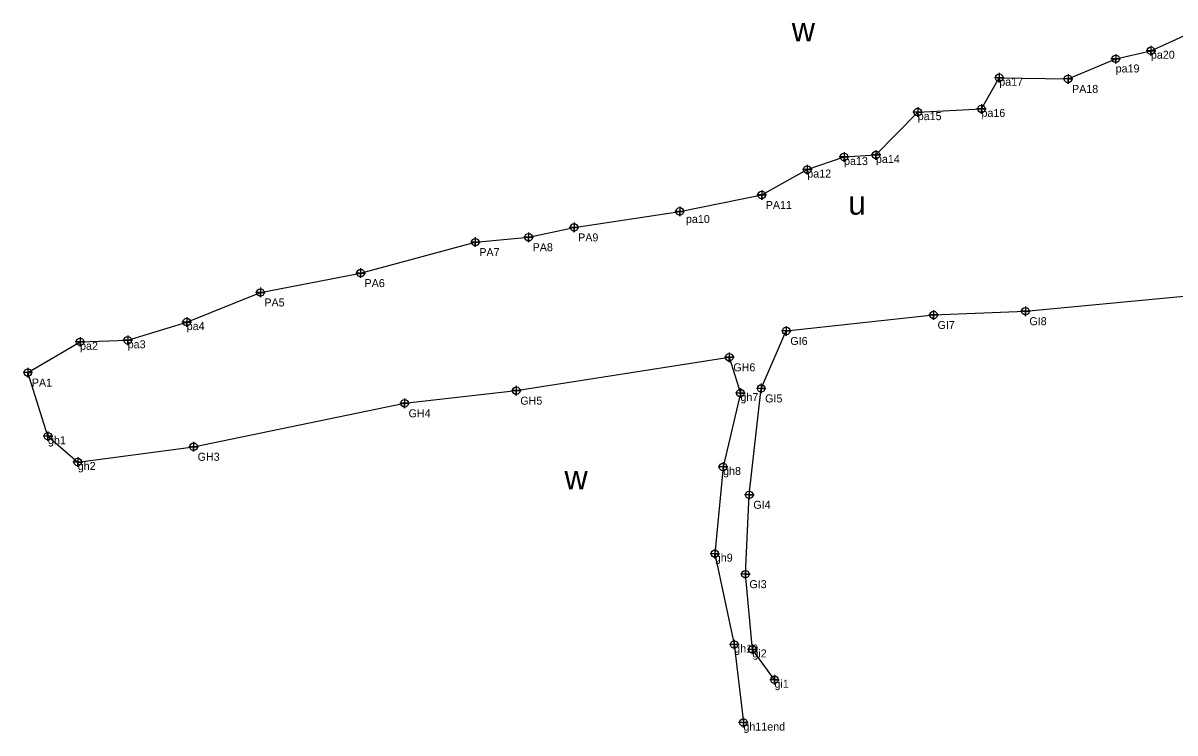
# Model space of a CAD drawing. Extents: x 2184390 to 2187551, y 452846 to 453752.
# Drawn here: x 2186121 to 2186840, y 453160 to 453604 of the extents above; entities that cross this region are included whole.
import ezdxf

# ---------------------------------------------------------------- set-up
doc = ezdxf.new("R2010")
doc.units = 0
for name, color, linetype in [('Exist Environmental Wetland Boundary', 7, 'Continuous'), ('Exist Environmental Wetland Boundary Cogo Comment', 7, 'Continuous'), ('Exist Environmental Wetland Boundary Cogo Point CELL', 7, 'Continuous'), ('Old_Level_52', 7, 'Continuous')]:
    doc.layers.add(name, color=color, linetype=linetype)

msp = doc.modelspace()

# ---------------------------------------------------------------- linework, layer by layer
at = {"layer": 'Exist Environmental Wetland Boundary'}
for points in [[(2186136.42, 453345.7), (2186123.85, 453385.42), (2186156.47, 453404.68), (2186186.24, 453405.63), (2186223.09, 453417.02), (2186269.09, 453435.52), (2186331.65, 453447.63), (2186403.33, 453466.98), (2186436.62, 453470.04), (2186465.03, 453476.17), (2186531, 453486.21), (2186582.21, 453496.45), (2186610.66, 453512.33), (2186633.62, 453520.2), (2186653.53, 453521.44), (2186679.64, 453548.24), (2186719.43, 453550.22), (2186730.56, 453569.74), (2186773.57, 453568.96), (2186803.32, 453581.55), (2186825.25, 453586.6), (2186859.95, 453602.41)], [(2186590.17, 453193.44), (2186576.37, 453212.42), (2186571.99, 453259.45), (2186574.44, 453309.06), (2186581.86, 453375.55), (2186597.55, 453411.45), (2186689.52, 453421.44), (2186746.86, 453423.8), (2186843.7, 453432.98), (2186967.92, 453449.19), (2187070.14, 453462.52), (2187156.63, 453463.76), (2187237.25, 453469.29), (2187303.93, 453487.14), (2187368.79, 453485.11), (2187436.86, 453480.5), (2187462.85, 453481.82), (2187471.15, 453496.67), (2187476.13, 453504.11)], [(2186136.42, 453345.7), (2186155.01, 453329.55), (2186227.4, 453339.07), (2186359.15, 453366.24), (2186428.91, 453374.15), (2186561.95, 453394.99), (2186568.89, 453372.66), (2186558.07, 453326.45), (2186552.91, 453272.26), (2186565.03, 453215.48), (2186570.77, 453166.7)]]:
    msp.add_lwpolyline(points, dxfattribs=at)
at = {"layer": 'Exist Environmental Wetland Boundary Cogo Point CELL'}
for points in [[(2186803.32, 453584.54), (2186803.32, 453578.54), (2186803.32, 453581.54), (2186806.32, 453581.54), (2186800.32, 453581.54)], [(2186825.25, 453589.6), (2186825.25, 453583.6), (2186825.25, 453586.6), (2186828.25, 453586.6), (2186822.25, 453586.6)], [(2186730.56, 453572.74), (2186730.56, 453566.74), (2186730.56, 453569.74), (2186733.56, 453569.74), (2186727.56, 453569.74)], [(2186773.5, 453571.98), (2186773.5, 453565.98), (2186773.5, 453568.98), (2186776.5, 453568.98), (2186770.5, 453568.98)], [(2186679.64, 453551.24), (2186679.64, 453545.24), (2186679.64, 453548.24), (2186682.64, 453548.24), (2186676.64, 453548.24)], [(2186719.43, 453553.22), (2186719.43, 453547.22), (2186719.43, 453550.22), (2186722.43, 453550.22), (2186716.43, 453550.22)], [(2186633.62, 453523.2), (2186633.62, 453517.2), (2186633.62, 453520.2), (2186636.62, 453520.2), (2186630.62, 453520.2)], [(2186653.53, 453524.44), (2186653.53, 453518.44), (2186653.53, 453521.44), (2186656.53, 453521.44), (2186650.53, 453521.44)], [(2186610.66, 453515.33), (2186610.66, 453509.33), (2186610.66, 453512.33), (2186613.66, 453512.33), (2186607.66, 453512.33)], [(2186582.21, 453499.45), (2186582.21, 453493.45), (2186582.21, 453496.45), (2186585.21, 453496.45), (2186579.21, 453496.45)], [(2186531, 453489.21), (2186531, 453483.21), (2186531, 453486.21), (2186534, 453486.21), (2186528, 453486.21)], [(2186465.03, 453479.17), (2186465.03, 453473.17), (2186465.03, 453476.17), (2186468.03, 453476.17), (2186462.03, 453476.17)], [(2186403.33, 453469.98), (2186403.33, 453463.98), (2186403.33, 453466.98), (2186406.33, 453466.98), (2186400.33, 453466.98)], [(2186436.62, 453473.04), (2186436.62, 453467.04), (2186436.62, 453470.04), (2186439.62, 453470.04), (2186433.62, 453470.04)], [(2186331.65, 453450.63), (2186331.65, 453444.63), (2186331.65, 453447.63), (2186334.65, 453447.63), (2186328.65, 453447.63)], [(2186269.09, 453438.52), (2186269.09, 453432.52), (2186269.09, 453435.52), (2186272.09, 453435.52), (2186266.09, 453435.52)], [(2186746.86, 453426.8), (2186746.86, 453420.8), (2186746.86, 453423.8), (2186749.87, 453423.8), (2186743.87, 453423.8)], [(2186223.09, 453420.02), (2186223.09, 453414.02), (2186223.09, 453417.02), (2186226.09, 453417.02), (2186220.09, 453417.02)], [(2186689.52, 453424.44), (2186689.52, 453418.44), (2186689.52, 453421.44), (2186692.52, 453421.44), (2186686.52, 453421.44)], [(2186597.55, 453414.45), (2186597.55, 453408.45), (2186597.55, 453411.45), (2186600.55, 453411.45), (2186594.55, 453411.45)], [(2186156.47, 453407.68), (2186156.47, 453401.68), (2186156.47, 453404.68), (2186159.47, 453404.68), (2186153.47, 453404.68)], [(2186186.24, 453408.63), (2186186.24, 453402.63), (2186186.24, 453405.63), (2186189.24, 453405.63), (2186183.24, 453405.63)], [(2186561.95, 453397.99), (2186561.95, 453391.99), (2186561.95, 453394.99), (2186564.95, 453394.99), (2186558.95, 453394.99)], [(2186123.85, 453388.42), (2186123.85, 453382.42), (2186123.85, 453385.42), (2186126.85, 453385.42), (2186120.85, 453385.42)], [(2186428.91, 453377.15), (2186428.91, 453371.15), (2186428.91, 453374.15), (2186431.91, 453374.15), (2186425.91, 453374.15)], [(2186568.89, 453375.66), (2186568.89, 453369.66), (2186568.89, 453372.66), (2186571.89, 453372.66), (2186565.89, 453372.66)], [(2186581.84, 453378.54), (2186581.84, 453372.54), (2186581.84, 453375.54), (2186584.84, 453375.54), (2186578.84, 453375.54)], [(2186359.15, 453369.24), (2186359.15, 453363.24), (2186359.15, 453366.24), (2186362.15, 453366.24), (2186356.15, 453366.24)], [(2186136.42, 453348.7), (2186136.42, 453342.7), (2186136.42, 453345.7), (2186139.42, 453345.7), (2186133.42, 453345.7)], [(2186227.4, 453342.07), (2186227.4, 453336.07), (2186227.4, 453339.07), (2186230.4, 453339.07), (2186224.4, 453339.07)], [(2186155.01, 453332.55), (2186155.01, 453326.55), (2186155.01, 453329.55), (2186158.01, 453329.55), (2186152.01, 453329.55)], [(2186558.07, 453329.45), (2186558.07, 453323.45), (2186558.07, 453326.45), (2186561.07, 453326.45), (2186555.07, 453326.45)], [(2186574.44, 453312.06), (2186574.44, 453306.06), (2186574.44, 453309.06), (2186577.44, 453309.06), (2186571.44, 453309.06)], [(2186552.91, 453275.26), (2186552.91, 453269.26), (2186552.91, 453272.26), (2186555.91, 453272.26), (2186549.91, 453272.26)], [(2186571.99, 453262.45), (2186571.99, 453256.45), (2186571.99, 453259.45), (2186574.99, 453259.45), (2186568.99, 453259.45)], [(2186565.03, 453218.48), (2186565.03, 453212.48), (2186565.03, 453215.48), (2186568.03, 453215.48), (2186562.03, 453215.48)], [(2186576.37, 453215.42), (2186576.37, 453209.42), (2186576.37, 453212.42), (2186579.37, 453212.42), (2186573.37, 453212.42)], [(2186590.17, 453196.44), (2186590.17, 453190.44), (2186590.17, 453193.44), (2186593.17, 453193.44), (2186587.17, 453193.44)], [(2186570.77, 453169.7), (2186570.77, 453163.7), (2186570.77, 453166.7), (2186573.77, 453166.7), (2186567.77, 453166.7)]]:
    msp.add_lwpolyline(points, dxfattribs=at)
for centre in [(2186803.32, 453581.54), (2186825.25, 453586.6), (2186730.56, 453569.74), (2186773.5, 453568.98), (2186679.64, 453548.24), (2186719.43, 453550.22), (2186633.62, 453520.2), (2186653.53, 453521.44), (2186610.66, 453512.33), (2186582.21, 453496.45), (2186531, 453486.21), (2186465.03, 453476.17), (2186403.33, 453466.98), (2186436.62, 453470.04), (2186331.65, 453447.63), (2186269.09, 453435.52), (2186746.86, 453423.8), (2186223.09, 453417.02), (2186689.52, 453421.44), (2186597.55, 453411.45), (2186156.47, 453404.68), (2186186.24, 453405.63), (2186561.95, 453394.99), (2186123.85, 453385.42), (2186428.91, 453374.15), (2186568.89, 453372.66), (2186581.84, 453375.54), (2186359.15, 453366.24), (2186136.42, 453345.7), (2186227.4, 453339.07), (2186155.01, 453329.55), (2186558.07, 453326.45), (2186574.44, 453309.06), (2186552.91, 453272.26), (2186571.99, 453259.45), (2186565.03, 453215.48), (2186576.37, 453212.42), (2186590.17, 453193.44), (2186570.77, 453166.7)]:
    msp.add_circle(centre, 2.34, dxfattribs=at)

# ---------------------------------------------------------------- texts
at = {"layer": 'Exist Environmental Wetland Boundary Cogo Comment'}
for s, p in [('pa20', (2186825.25, 453581.6)), ('pa19', (2186803.26, 453573.02)), ('pa17', (2186730.56, 453564.74)), ('PA18', (2186776, 453560.23)), ('pa15', (2186679.64, 453543.24)), ('pa16', (2186719.43, 453545.22)), ('pa13', (2186633.62, 453515.2)), ('pa14', (2186653.53, 453516.44)), ('pa12', (2186610.66, 453507.33)), ('PA11', (2186584.71, 453487.7)), ('pa10', (2186534.87, 453478.93)), ('PA9', (2186467.53, 453467.42)), ('PA7', (2186405.83, 453458.23)), ('PA8', (2186439.12, 453461.29)), ('PA6', (2186334.15, 453438.88)), ('PA5', (2186271.59, 453426.77)), ('GI8', (2186749.37, 453415.05)), ('pa4', (2186223.09, 453412.02)), ('GI7', (2186692.02, 453412.69)), ('pa2', (2186156.47, 453399.68)), ('pa3', (2186186.24, 453400.63)), ('GI6', (2186600.05, 453402.7)), ('GH6', (2186564.45, 453386.24)), ('PA1', (2186126.35, 453376.67)), ('GH5', (2186431.41, 453365.4)), ('gh7', (2186568.89, 453367.66)), ('GI5', (2186584.34, 453366.79)), ('GH4', (2186361.65, 453357.49)), ('gh1', (2186136.42, 453340.7)), ('GH3', (2186229.9, 453330.32)), ('gh2', (2186155.01, 453324.55)), ('gh8', (2186558.07, 453321.45)), ('GI4', (2186576.94, 453300.31)), ('gh9', (2186552.91, 453267.26)), ('GI3', (2186574.49, 453250.7)), ('gh10', (2186565.03, 453210.48)), ('gi2', (2186576.37, 453207.42)), ('gi1', (2186590.17, 453188.44)), ('gh11end', (2186570.77, 453161.7))]:
    msp.add_text(s, height=5, dxfattribs=at).set_placement(p)
at = {"layer": 'Old_Level_52'}
for s, p in [('w', (2186600.97, 453592.41)), ('u', (2186636.14, 453484.16)), ('w', (2186459.02, 453312.37))]:
    msp.add_text(s, height=15, dxfattribs=at).set_placement(p)

doc.saveas('drawing.dxf')
